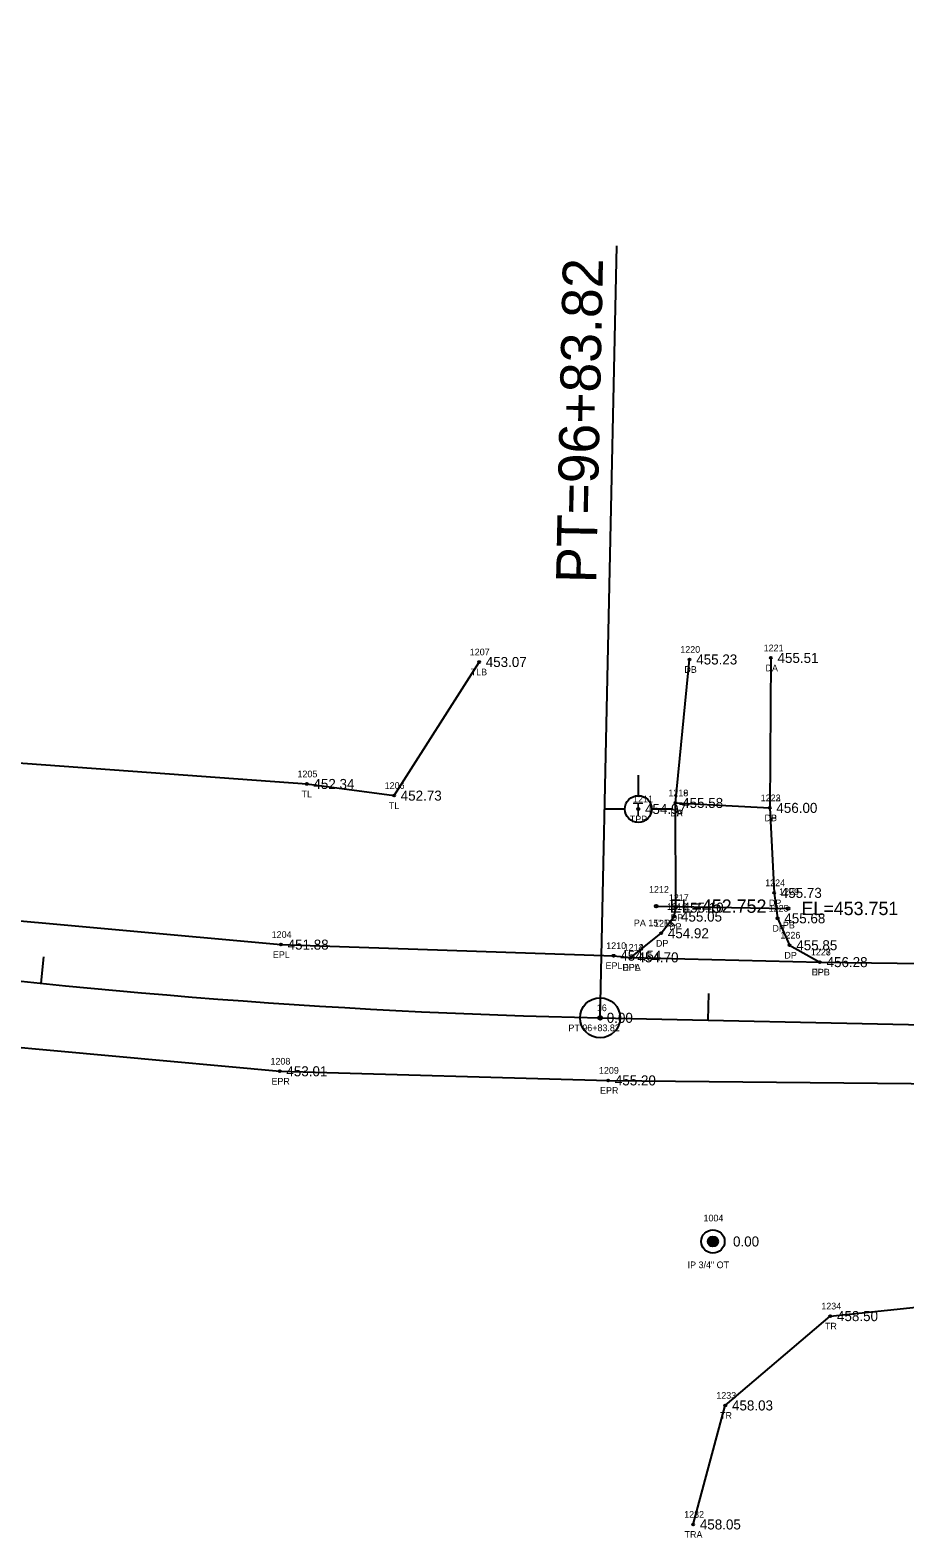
# Model space of a CAD drawing. Extents: x 1809463 to 1812121, y 790645 to 791946.
# Drawn here: x 1811195.4 to 1811326.2, y 791067.8 to 791293.5 of the extents above; entities that cross this region are included whole.
import ezdxf

# ---------------------------------------------------------------- set-up
doc = ezdxf.new("R2010")
doc.units = 0
for name, color, linetype in [('RD_EX_DR_Pipe', 7, 'Continuous'), ('RD_EX_DR_Pipe_txCode', 7, 'Continuous'), ('RD_EX_Driveway', 7, 'Continuous'), ('RD_EX_Driveway_txCode', 7, 'Continuous'), ('RD_EX_DV_Prop_txCode', 7, 'Continuous'), ('RD_EX_DV_PropPin', 7, 'Continuous'), ('RD_EX_Road', 7, 'Continuous'), ('RD_EX_Road_txCode', 7, 'Continuous'), ('RD_EX_TX_Driveway_ELEV', 7, 'Continuous'), ('RD_EX_TX_DV_Prop_ELEV', 7, 'Continuous'), ('RD_EX_TX_Road_ELEV', 7, 'Continuous'), ('RD_EX_TX_UT_ELEV', 7, 'Continuous'), ('RD_EX_TX_VEG_ELEV', 7, 'Continuous'), ('RD_EX_UT', 7, 'Continuous'), ('RD_EX_UT_txCode', 7, 'Continuous'), ('RD_EX_VEG', 7, 'Continuous'), ('RD_EX_VEG_txCode', 7, 'Continuous'), ('RD_HC_Cl', 7, 'Continuous'), ('RD_HC_Data', 7, 'Continuous'), ('RD_HC_Data_Tic', 7, 'Continuous'), ('RD_HC_Survey_ELEV', 7, 'Continuous'), ('RD_HC_txCode', 7, 'Continuous'), ('RD_SMD_Locator', 7, 'Continuous'), ('RD_TX_Pipe_ElevEX', 7, 'Continuous')]:
    doc.layers.add(name, color=color, linetype=linetype)

msp = doc.modelspace()

# ---------------------------------------------------------------- linework, layer by layer
at = {"layer": 'RD_EX_DR_Pipe'}
msp.add_line((1811289.04, 791162.34), (1811308.78, 791162), dxfattribs=at)
at = {"layer": 'RD_EX_Driveway'}
for p, q in [((1811306.2, 791199.5), (1811306.03, 791177.05)), ((1811291.93, 791177.79), (1811294.04, 791199.27))]:
    msp.add_line(p, q, dxfattribs=at)
msp.add_lwpolyline([(1811285.25, 791154.67), (1811289.79, 791158.28), (1811291.76, 791160.78), (1811292, 791162.12), (1811291.93, 791177.79), (1811306.03, 791177.05), (1811306.69, 791164.33), (1811307.22, 791160.52), (1811309.01, 791156.49), (1811313.54, 791153.96)], dxfattribs=at)
at = {"layer": 'RD_EX_DV_PropPin'}
for p, q in [((1811296.81, 791111.94), (1811296.81, 791112.34)), ((1811296.84, 791111.84), (1811296.84, 791112.44)), ((1811296.88, 791111.77), (1811296.88, 791112.51)), ((1811296.91, 791111.71), (1811296.91, 791112.57)), ((1811296.95, 791111.67), (1811296.95, 791112.61)), ((1811296.98, 791111.63), (1811296.98, 791112.66)), ((1811297.02, 791111.59), (1811297.02, 791112.69)), ((1811297.05, 791111.56), (1811297.05, 791112.72)), ((1811297.09, 791111.53), (1811297.09, 791112.75)), ((1811297.12, 791111.51), (1811297.12, 791112.77)), ((1811297.16, 791111.48), (1811297.16, 791112.8)), ((1811297.19, 791111.46), (1811297.19, 791112.82)), ((1811297.23, 791111.45), (1811297.23, 791112.83)), ((1811297.26, 791111.43), (1811297.26, 791112.85)), ((1811297.3, 791111.42), (1811297.3, 791112.86)), ((1811297.33, 791111.41), (1811297.33, 791112.87)), ((1811297.37, 791111.4), (1811297.37, 791112.88)), ((1811297.4, 791111.39), (1811297.4, 791112.89)), ((1811297.44, 791111.39), (1811297.44, 791112.89)), ((1811297.47, 791111.38), (1811297.47, 791112.9)), ((1811297.51, 791111.38), (1811297.51, 791112.9)), ((1811297.54, 791111.38), (1811297.54, 791112.9)), ((1811297.58, 791111.38), (1811297.58, 791112.9)), ((1811297.61, 791111.38), (1811297.61, 791112.9)), ((1811297.65, 791111.39), (1811297.65, 791112.89)), ((1811297.68, 791111.39), (1811297.68, 791112.89)), ((1811297.72, 791111.4), (1811297.72, 791112.88)), ((1811297.75, 791111.41), (1811297.75, 791112.87)), ((1811297.79, 791111.42), (1811297.79, 791112.86)), ((1811297.82, 791111.43), (1811297.82, 791112.85)), ((1811297.86, 791111.45), (1811297.86, 791112.83)), ((1811297.89, 791111.46), (1811297.89, 791112.82)), ((1811297.93, 791111.48), (1811297.93, 791112.8)), ((1811297.96, 791111.51), (1811297.96, 791112.77)), ((1811298, 791111.53), (1811298, 791112.75)), ((1811298.03, 791111.56), (1811298.03, 791112.72)), ((1811298.07, 791111.59), (1811298.07, 791112.69)), ((1811298.11, 791111.63), (1811298.11, 791112.66)), ((1811298.14, 791111.67), (1811298.14, 791112.61)), ((1811298.18, 791111.71), (1811298.18, 791112.57)), ((1811298.21, 791111.77), (1811298.21, 791112.51)), ((1811298.25, 791111.84), (1811298.25, 791112.44)), ((1811298.28, 791111.94), (1811298.28, 791112.34))]:
    msp.add_line(p, q, dxfattribs=at)
for radius in [1.75, 0.761]:
    msp.add_circle((1811297.54, 791112.14), radius, dxfattribs=at)
at = {"layer": 'RD_EX_Road'}
for points in [[(1810807.88, 791282.84), (1810852, 791259.68), (1810897.52, 791238.67), (1810942.78, 791219.24), (1810989.92, 791202.01), (1811037.03, 791187.9), (1811084.94, 791176.28), (1811134.78, 791167.28), (1811183.92, 791161.02), (1811232.9, 791156.58), (1811282.68, 791154.92), (1811285.25, 791154.67), (1811313.54, 791153.96), (1811332.83, 791153.68), (1811383.78, 791152.53), (1811433.81, 791151.61), (1811483.97, 791148.18)], [(1810799.46, 791266.97), (1810843.53, 791244.35), (1810889.8, 791222.88), (1810936.32, 791202.72), (1810983.79, 791185.28), (1811031.51, 791170.21), (1811081.62, 791158.02), (1811131.99, 791148.92), (1811148.3, 791146.24), (1811177.02, 791142.75), (1811182.52, 791142.23), (1811232.71, 791137.62), (1811281.86, 791136.25), (1811332.25, 791135.72), (1811383.92, 791134.19), (1811422.24, 791132.82), (1811433.21, 791132.2), (1811452.43, 791131.25), (1811482.29, 791129.59)]]:
    msp.add_lwpolyline(points, dxfattribs=at)
at = {"layer": 'RD_EX_UT'}
for p, q in [((1811286.37, 791181.95), (1811286.37, 791178.88)), ((1811281.44, 791176.9), (1811284.37, 791176.9)), ((1811288.37, 791176.9), (1811291.44, 791176.9))]:
    msp.add_line(p, q, dxfattribs=at)
msp.add_circle((1811286.37, 791176.88), 2, dxfattribs=at)
at = {"layer": 'RD_EX_VEG'}
for points in [[(1810341.02, 791567.09), (1810359.88, 791551.99), (1810422.51, 791511.77), (1810509.88, 791459.82), (1810597.87, 791416.6), (1810690.3, 791371.23), (1810825.66, 791316.88), (1810866.79, 791289.5), (1810909.83, 791263.61), (1810951.77, 791236.76), (1810996.45, 791220.63), (1811044.92, 791210.53), (1811089.45, 791196.27), (1811139.01, 791190.33), (1811186.69, 791184.29), (1811236.76, 791180.63), (1811249.82, 791178.89), (1811262.54, 791198.89)], [(1811294.58, 791069.77), (1811299.39, 791087.59), (1811315.1, 791100.96), (1811332.24, 791102.74), (1811381.42, 791102.88), (1811419.25, 791096.28), (1811414.75, 791071.22)]]:
    msp.add_lwpolyline(points, dxfattribs=at)
at = {"layer": 'RD_HC_Cl'}
msp.add_line((1811280.65, 791145.62), (1811427.69, 791142.45), dxfattribs=at)
msp.add_arc((1811303.09, 792187.12), 1041.74, 241.96114, 268.76562, dxfattribs=at)
at = {"layer": 'RD_HC_Data'}
msp.add_line((1811280.65, 791145.62), (1811283.14, 791261.18), dxfattribs=at)
for radius in [3, 0.282]:
    msp.add_circle((1811280.65, 791145.62), radius, dxfattribs=at)
at = {"layer": 'RD_HC_Data_Tic'}
for p, q in [((1811197, 791150.79), (1811197.41, 791154.77)), ((1811296.82, 791145.27), (1811296.9, 791149.27))]:
    msp.add_line(p, q, dxfattribs=at)
at = {"layer": 'RD_SMD_Locator'}
for centre, radius in [((1811294.04, 791199.27), 0.15), ((1811306.2, 791199.5), 0.15), ((1811262.54, 791198.89), 0.15), ((1811236.76, 791180.63), 0.15), ((1811249.82, 791178.89), 0.15), ((1811286.37, 791176.88), 0.15), ((1811291.93, 791177.79), 0.15), ((1811291.93, 791177.79), 0.15), ((1811306.03, 791177.05), 0.15), ((1811306.03, 791177.05), 0.15), ((1811306.69, 791164.33), 0.15), ((1811289.04, 791162.34), 0.2), ((1811292, 791162.12), 0.15), ((1811308.78, 791162), 0.2), ((1811291.76, 791160.78), 0.15), ((1811307.22, 791160.52), 0.15), ((1811232.9, 791156.58), 0.15), ((1811289.79, 791158.28), 0.15), ((1811309.01, 791156.49), 0.15), ((1811282.68, 791154.92), 0.15), ((1811285.25, 791154.67), 0.15), ((1811285.25, 791154.67), 0.15), ((1811313.54, 791153.96), 0.15), ((1811313.54, 791153.96), 0.15), ((1811280.65, 791145.62), 0.15), ((1811232.71, 791137.62), 0.15), ((1811281.86, 791136.25), 0.15), ((1811297.54, 791112.14), 0.15), ((1811315.1, 791100.96), 0.15), ((1811299.39, 791087.59), 0.15), ((1811294.58, 791069.77), 0.15)]:
    msp.add_circle(centre, radius, dxfattribs=at)

# ---------------------------------------------------------------- texts
at = {"layer": 'RD_EX_DR_Pipe_txCode'}
for s, p in [('1212', (1811287.97, 791164.34)), ('1229', (1811307.44, 791164)), ('PA 15" RC', (1811285.71, 791159.34)), ('PB', (1811308, 791159))]:
    msp.add_text(s, height=1, dxfattribs=at).set_placement(p)
at = {"layer": 'RD_EX_Driveway_txCode'}
for s, p in [('1220', (1811292.65, 791200.27)), ('1221', (1811305.13, 791200.5)), ('DB', (1811293.26, 791197.27)), ('DA', (1811305.4, 791197.5)), ('1218', (1811290.87, 791178.79)), ('1219', (1811290.87, 791178.79)), ('1222', (1811304.69, 791178.05)), ('1223', (1811304.69, 791178.05)), ('DA', (1811291.13, 791175.79)), ('DP', (1811291.15, 791175.79)), ('DB', (1811305.25, 791175.05)), ('DP', (1811305.25, 791175.05)), ('1224', (1811305.35, 791165.33)), ('1217', (1811290.94, 791163.12)), ('DP', (1811305.91, 791162.33)), ('1216', (1811290.67, 791161.78)), ('DP', (1811291.22, 791160.12)), ('1225', (1811305.88, 791161.52)), ('1215', (1811288.73, 791159.28)), ('DP', (1811290.98, 791158.78)), ('DP', (1811306.44, 791158.52)), ('1214', (1811284.18, 791155.67)), ('DP', (1811289.01, 791156.28)), ('1226', (1811307.64, 791157.49)), ('DP', (1811308.23, 791154.49)), ('1227', (1811312.19, 791154.96)), ('DPA', (1811283.98, 791152.67)), ('DPB', (1811312.28, 791151.96))]:
    msp.add_text(s, height=1, dxfattribs=at).set_placement(p)
at = {"layer": 'RD_EX_DV_Prop_txCode'}
for s, p in [('1004', (1811296.12, 791115.14)), ('IP 3/4" OT', (1811293.75, 791108.14))]:
    msp.add_text(s, height=1, dxfattribs=at).set_placement(p)
at = {"layer": 'RD_EX_Road_txCode'}
for s, p in [('1204', (1811231.51, 791157.58)), ('1210', (1811281.57, 791155.92)), ('1213', (1811284.18, 791155.67)), ('EPL', (1811231.69, 791154.58)), ('1228', (1811312.19, 791154.96)), ('EPL', (1811281.47, 791152.92)), ('EPL', (1811284.04, 791152.67)), ('EPL', (1811312.33, 791151.96)), ('1208', (1811231.33, 791138.62)), ('EPR', (1811231.48, 791135.62)), ('1209', (1811280.48, 791137.25)), ('EPR', (1811280.64, 791134.25))]:
    msp.add_text(s, height=1, dxfattribs=at).set_placement(p)
at = {"layer": 'RD_EX_TX_Driveway_ELEV'}
for s, p in [('455.23', (1811295.04, 791198.52)), ('455.51', (1811307.2, 791198.75)), ('455.58', (1811292.93, 791177.04)), ('455.58', (1811292.93, 791177.04)), ('456.00', (1811307.03, 791176.3)), ('456.00', (1811307.03, 791176.3)), ('455.73', (1811307.69, 791163.58)), ('455.05', (1811292.76, 791160.03)), ('455.10', (1811293, 791161.37)), ('455.68', (1811308.22, 791159.77)), ('454.92', (1811290.79, 791157.53)), ('455.85', (1811310.01, 791155.74)), ('454.70', (1811286.25, 791153.92)), ('456.28', (1811314.54, 791153.21))]:
    msp.add_text(s, height=1.5, dxfattribs=at).set_placement(p)
at = {"layer": 'RD_EX_TX_DV_Prop_ELEV'}
msp.add_text('0.00', height=1.5, dxfattribs=at).set_placement((1811300.54, 791111.39))
at = {"layer": 'RD_EX_TX_Road_ELEV'}
for s, p in [('451.88', (1811233.9, 791155.83)), ('454.54', (1811283.68, 791154.17)), ('454.70', (1811286.25, 791153.92)), ('456.28', (1811314.54, 791153.21)), ('453.01', (1811233.71, 791136.87)), ('455.20', (1811282.86, 791135.5))]:
    msp.add_text(s, height=1.5, dxfattribs=at).set_placement(p)
at = {"layer": 'RD_EX_TX_UT_ELEV'}
msp.add_text('454.97', height=1.5, dxfattribs=at).set_placement((1811287.37, 791176.13))
at = {"layer": 'RD_EX_TX_VEG_ELEV'}
for s, p in [('453.07', (1811263.54, 791198.14)), ('452.34', (1811237.76, 791179.88)), ('452.73', (1811250.82, 791178.14)), ('458.50', (1811316.1, 791100.21)), ('458.03', (1811300.39, 791086.84)), ('458.05', (1811295.58, 791069.02))]:
    msp.add_text(s, height=1.5, dxfattribs=at).set_placement(p)
at = {"layer": 'RD_EX_UT'}
msp.add_text('T', height=2, dxfattribs=at).set_placement((1811285.52, 791175.83))
at = {"layer": 'RD_EX_UT_txCode'}
for s, p in [('1211', (1811285.59, 791177.88)), ('TPP', (1811285.1, 791174.88))]:
    msp.add_text(s, height=1, dxfattribs=at).set_placement(p)
at = {"layer": 'RD_EX_VEG_txCode'}
for s, p in [('1207', (1811261.15, 791199.89)), ('TLB', (1811261.29, 791196.89)), ('1205', (1811235.37, 791181.63)), ('TL', (1811235.98, 791178.63)), ('1206', (1811248.42, 791179.89)), ('TL', (1811249.05, 791176.89)), ('1234', (1811313.75, 791101.96)), ('TR', (1811314.3, 791098.96)), ('1233', (1811298.04, 791088.59)), ('TR', (1811298.6, 791085.59)), ('1232', (1811293.23, 791070.77)), ('TRA', (1811293.29, 791067.77))]:
    msp.add_text(s, height=1, dxfattribs=at).set_placement(p)
at = {"layer": 'RD_HC_Data'}
msp.add_text('PT=96+83.82', height=6, rotation=88.7656, dxfattribs=at).set_placement((1811280.05, 791210.65))
at = {"layer": 'RD_HC_Survey_ELEV'}
msp.add_text('0.00', height=1.5, dxfattribs=at).set_placement((1811281.65, 791144.87))
at = {"layer": 'RD_HC_txCode'}
for s, p in [('16', (1811280.17, 791146.62)), ('PT 96+83.82', (1811275.91, 791143.62))]:
    msp.add_text(s, height=1, dxfattribs=at).set_placement(p)
at = {"layer": 'RD_TX_Pipe_ElevEX'}
for s, p in [('EL=452.752', (1811291.04, 791161.34)), ('EL=453.751', (1811310.78, 791161))]:
    msp.add_text(s, height=2, dxfattribs=at).set_placement(p)

doc.saveas('drawing.dxf')
